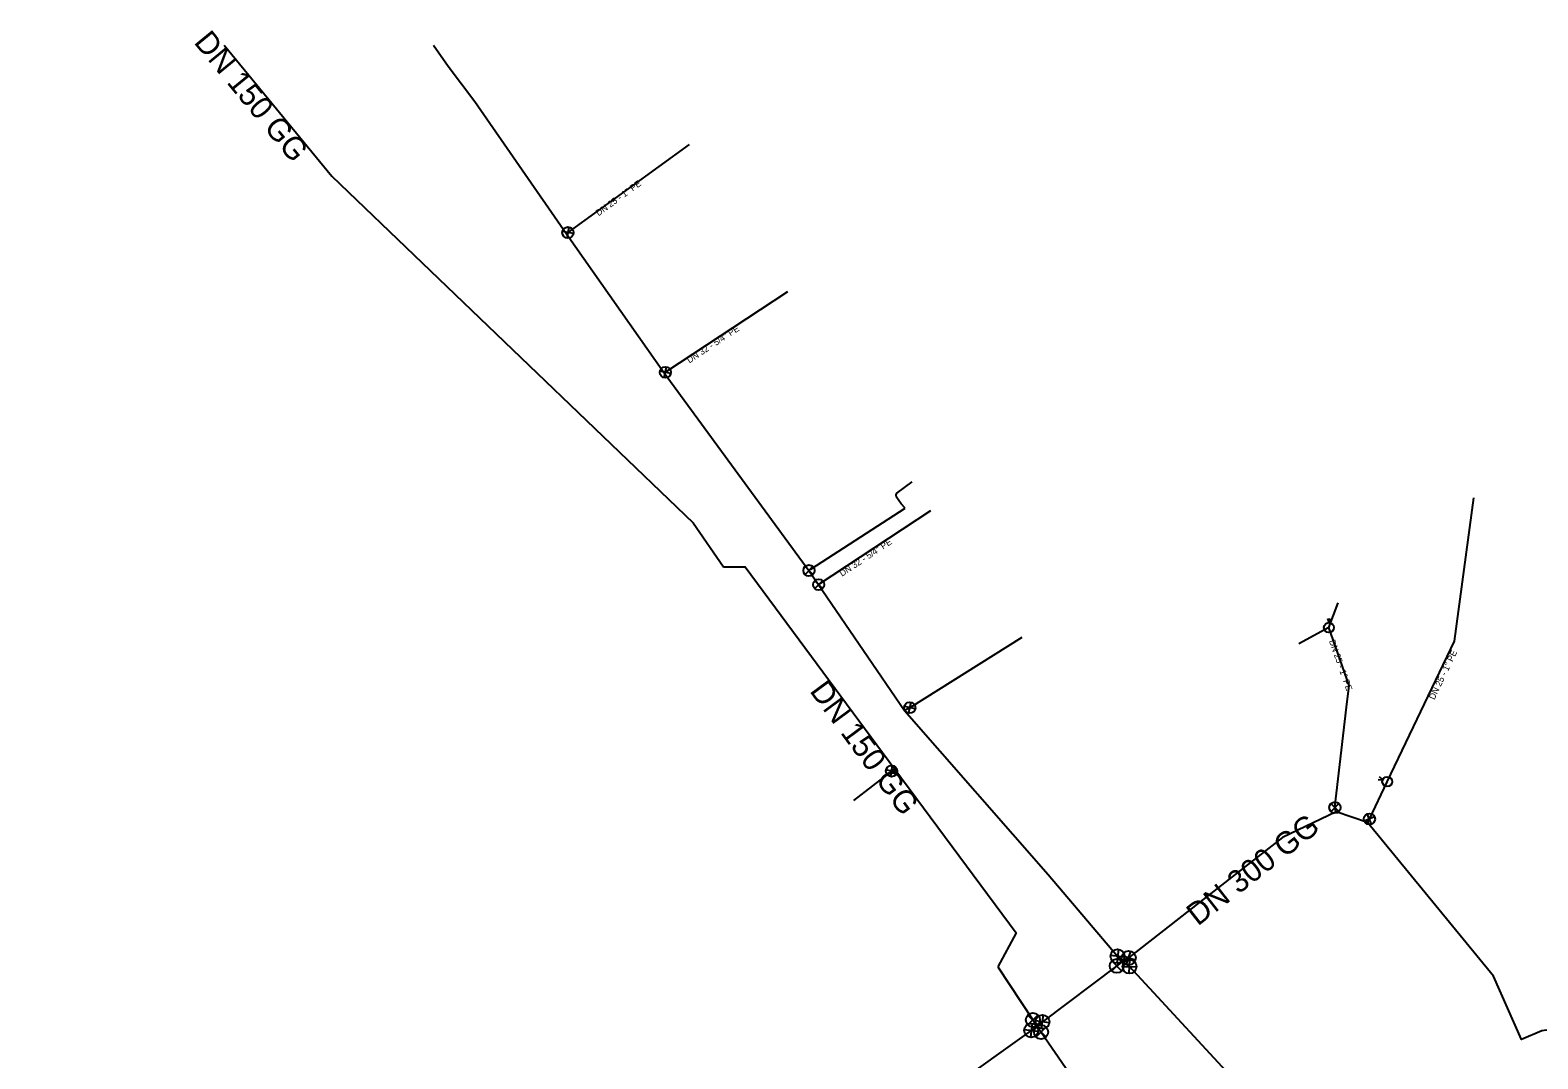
# Model space of a CAD drawing. Extents: x -4927528 to -4924018, y -11264917 to -11262544.
# Drawn here: x -4926456 to -4925380, y -11263278 to -11262544 of the extents above; entities that cross this region are included whole.
import ezdxf

# ---------------------------------------------------------------- set-up
doc = ezdxf.new("R2010")
doc.units = 0
for name, color, linetype in [('_pripojka_prevzato_z_dokumentace_', 7, 'Continuous'), ('_pripojka_priblizne_', 7, 'Continuous'), ('_voda_smvak_prevzato_z_dokumentace_', 7, 'Continuous'), ('Default', 7, 'Continuous'), ('MoLevel 27', 7, 'Continuous'), ('MoLevel 30', 7, 'Continuous'), ('MoLevel 32', 7, 'Continuous'), ('MoLevel 46', 7, 'Continuous'), ('MoLevel 53', 7, 'Continuous'), ('MoLevel 55', 7, 'Continuous')]:
    doc.layers.add(name, color=color, linetype=linetype)

# ---------------------------------------------------------------- blocks, each defined once
blk = doc.blocks.new('_uzaver_')
at = {"layer": 'Default'}
for p, q in [((-0.00035, -0.00035), (0.00035, 0.00035)), ((0.00035, -0.00035), (-0.00035, 0.00035))]:
    blk.add_line(p, q, dxfattribs=at)
for radius in [0.0005, 0.000025]:
    blk.add_circle((0, 0), radius, dxfattribs=at)
blk = doc.blocks.new('_uzaver_pripojka_')
at = {"layer": 'Default'}
for p, q in [((-0.00035, -0.00035), (0.00035, 0.00035)), ((0.00035, -0.00035), (-0.00035, 0.00035))]:
    blk.add_line(p, q, dxfattribs=at)
for radius in [0.0005, 0.000025]:
    blk.add_circle((0, 0), radius, dxfattribs=at)
blk = doc.blocks.new('_sachta_voda_')
at = {"layer": 'Default'}
blk.add_lwpolyline([(-0.0001, 0.00065), (0, 0.00035), (0.0001, 0.00065)], dxfattribs=at)
blk.add_circle((0, 0), 0.00035, dxfattribs=at)

msp = doc.modelspace()

# ---------------------------------------------------------------- linework, layer by layer
at = {"layer": '_pripojka_prevzato_z_dokumentace_'}
msp.add_line((-4925529.5, -11262970.3), (-4925522.8, -11262952.7), dxfattribs=at)
for points in [[(-4925985.7, -11262625.6), (-4926072.2, -11262688.5), (-4926073.1, -11262689.4)], [(-4925915.6, -11262730.8), (-4926002.7, -11262788.2), (-4926003.6, -11262788.6)], [(-4925487.9, -11263080.3), (-4925440, -11262980.1), (-4925426.2, -11262877.7)], [(-4925748.6, -11262977.3), (-4925828.4, -11263027.5), (-4925832.1, -11263029.5)], [(-4925516.9, -11263027.2), (-4925515, -11263011.7), (-4925529.5, -11262970.3), (-4925551, -11262982)], [(-4925524.2, -11263101.8), (-4925525.2, -11263098.7), (-4925516.9, -11263027.2)], [(-4925839, -11263071.4), (-4925841.4, -11263072.7), (-4925868.6, -11263093.8)], [(-4925502, -11263109.5), (-4925500.6, -11263106.9), (-4925487.9, -11263080.3)]]:
    msp.add_lwpolyline(points, dxfattribs=at)
at = {"layer": '_pripojka_priblizne_'}
msp.add_line((-4925893.4, -11262939.7), (-4925813.4, -11262886.8), dxfattribs=at)
for points in [[(-4925831.8, -11262885.1), (-4925834.5, -11262882.1), (-4925837.8, -11262877.2), (-4925838, -11262875.6), (-4925837.6, -11262874.5), (-4925826.6, -11262866.3)], [(-4925900.3, -11262929.6), (-4925899, -11262928.6), (-4925831.8, -11262885.1)]]:
    msp.add_lwpolyline(points, dxfattribs=at)
at = {"layer": '_voda_smvak_prevzato_z_dokumentace_'}
for p, q in [((-4925765.7, -11263212.3), (-4925740.6, -11263250.3)), ((-4925680.8, -11263211.7), (-4925733.8, -11263251.6)), ((-4925676.6, -11263208.6), (-4925680.8, -11263211.7)), ((-4925680.2, -11263204.8), (-4925676.6, -11263208.6)), ((-4925672.3, -11263206), (-4925676.6, -11263208.6)), ((-4925671.7, -11263212.2), (-4925676.6, -11263208.6)), ((-4925410.7, -11263494.2), (-4925671.7, -11263212.2)), ((-4925737.7, -11263254.7), (-4925741.8, -11263257.7)), ((-4925740.6, -11263250.3), (-4925737.7, -11263254.7)), ((-4925733.8, -11263251.6), (-4925737.7, -11263254.7)), ((-4925737.7, -11263254.7), (-4925734.8, -11263258.9)), ((-4925734.8, -11263258.9), (-4925542, -11263538.9))]:
    msp.add_line(p, q, dxfattribs=at)
for points in [[(-4926317.3, -11262554.7), (-4926240.5, -11262648.3), (-4925982.9, -11262895.5), (-4925961.2, -11262926.9)], [(-4926168.1, -11262554.7), (-4926157.6, -11262569.8), (-4926138.7, -11262594.9), (-4926073.1, -11262689.4), (-4926003.6, -11262788.6), (-4925900.3, -11262929.6), (-4925832.1, -11263029.5), (-4925729.8, -11263146.6), (-4925680.2, -11263204.8)], [(-4925961.2, -11262926.9), (-4925945.9, -11262927), (-4925839, -11263071.4), (-4925752.5, -11263188.2), (-4925765.7, -11263212.3)], [(-4925356.8, -11263255.1), (-4925377.7, -11263258.1), (-4925392.2, -11263264.1), (-4925412, -11263219.1), (-4925502, -11263109.5), (-4925524.2, -11263101.8), (-4925562.6, -11263120), (-4925672.3, -11263206)], [(-4925741.8, -11263257.7), (-4926471.3, -11263779.7), (-4926626.3, -11263906.7), (-4926783.8, -11264042.7), (-4926826.3, -11264075.2), (-4926870.7, -11264137), (-4927005.3, -11264324.4), (-4927247.9, -11264639.2), (-4927375.4, -11264800)]]:
    msp.add_lwpolyline(points, dxfattribs=at)

# ---------------------------------------------------------------- block references
at = {"layer": 'MoLevel 27'}
for p, xscale, yscale, rotation in [((-4925680.2, -11263204.8), 10000, 10000, 128.441457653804), ((-4925672.3, -11263206), 10000, 10000.000000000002, 27.043191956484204), ((-4925671.7, -11263212.2), 10000.000000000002, 9999.999999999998, -46.520326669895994), ((-4925733.8, -11263251.6), 10000, 10000, 37.3442694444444), ((-4925741.8, -11263257.7), 10000, 10000, -142.15966870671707)]:
    msp.add_blockref('_uzaver_', p, dxfattribs=dict(at, xscale=xscale, yscale=yscale, rotation=rotation))
at = {"layer": 'MoLevel 27', "xscale": 10000, "yscale": 10000}
for p in [(-4925680.8, -11263211.7), (-4925740.6, -11263250.3), (-4925734.8, -11263258.9)]:
    msp.add_blockref('_uzaver_', p, dxfattribs=at)
at = {"layer": 'MoLevel 30', "xscale": 10000, "yscale": 10000}
msp.add_blockref('_sachta_voda_', (-4925529.5, -11262970.3), dxfattribs=at)
at = {"layer": 'MoLevel 30', "xscale": 10000, "yscale": 10000, "rotation": 67.2491527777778}
msp.add_blockref('_sachta_voda_', (-4925487.9, -11263080.3), dxfattribs=at)
at = {"layer": 'MoLevel 53'}
for p, xscale, yscale, rotation in [((-4926072.2, -11262688.5), 7999.999999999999, 7999.999999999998, 124.865247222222), ((-4926002.7, -11262788.2), 8000, 7999.999999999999, 32.9463555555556), ((-4925828.4, -11263027.5), 7999.999999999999, 8000.000000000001, 123.391855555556), ((-4925841.4, -11263072.7), 8000, 7999.999999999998, 35.9496055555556), ((-4925525.2, -11263098.7), 8000, 7999.999999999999, -89.91195555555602), ((-4925500.6, -11263106.9), 7999.999999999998, 8000.000000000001, 67.2491527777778)]:
    msp.add_blockref('_uzaver_pripojka_', p, dxfattribs=dict(at, xscale=xscale, yscale=yscale, rotation=rotation))
at = {"layer": 'MoLevel 53', "xscale": 7999.999999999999, "yscale": 7999.999999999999}
for p in [(-4925900.3, -11262929.6), (-4925893.4, -11262939.7)]:
    msp.add_blockref('_uzaver_pripojka_', p, dxfattribs=at)

# ---------------------------------------------------------------- texts
at = {"layer": 'MoLevel 32'}
msp.add_text("DN 32 - 5/4'' PE", height=4.55, rotation=33.4566, dxfattribs=at).set_placement((-4925876.7, -11262934.1))
at = {"layer": 'MoLevel 46'}
for s, rotation, p in [('DN 150 GG', 309.3656, (-4926339.5, -11262552.9)), ('DN 150 GG', 306.5184, (-4925900.3, -11263015.6)), ('DN 300 GG', 38.0972, (-4925623, -11263183.7))]:
    msp.add_text(s, height=16.05, rotation=rotation, dxfattribs=at).set_placement(p)
at = {"layer": 'MoLevel 55'}
for s, rotation, p in [("DN 25 - 1'' PE", 36.0309, (-4926050.3, -11262676.9)), ("DN 32 - 5/4'' PE", 33.3641, (-4925985.6, -11262781.9)), ("DN 25 - 1'' PE", 289.3031, (-4925529.5, -11262979.9)), ("DN 25 - 1'' PE", 64.4778, (-4925454.3, -11263022.2))]:
    msp.add_text(s, height=4.55, rotation=rotation, dxfattribs=at).set_placement(p)

doc.saveas('drawing.dxf')
